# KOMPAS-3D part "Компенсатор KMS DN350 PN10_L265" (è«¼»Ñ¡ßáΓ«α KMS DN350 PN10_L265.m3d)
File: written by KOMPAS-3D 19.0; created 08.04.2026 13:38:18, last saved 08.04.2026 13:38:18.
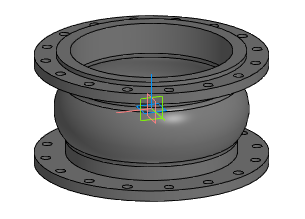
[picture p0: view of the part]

Document properties: Автор: Энергия; Полное имя файла: Z:\3.Личные\kachalov\3d для проектировщиков\7.1 Компенсатор\stp_Компенсатор KSM\Компенсатор KMS DN350 PN10_L265.m3d

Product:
- Part/product: Компенсатор KMS DN350 PN10_L265

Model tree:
1. Операция без истории:1  (labels: Компенсатор KMS DN350 PN10_L265)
